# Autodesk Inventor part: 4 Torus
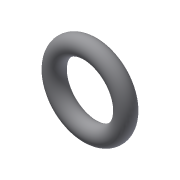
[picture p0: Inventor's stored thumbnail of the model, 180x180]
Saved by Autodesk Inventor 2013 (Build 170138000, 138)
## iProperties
Created: 2012-10
Part Number: 4 Torus
Material: Allgemein
Vendor: www.inventor-faq.de
Document SubType Name: Modeling
Designer: Administrator
Manufacturer: www.inventor-faq.de
Density: 1 g/cm^3
RuleStatus: InUse
AfterDocOpen0: inventorfaq
BeforeDocSave0: inventorfaq
Author: Administrator
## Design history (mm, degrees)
sketch "Skizze1"
  geometry: L1 (0, 2.5)-(0, -2.5); L2 (0, 0)-(-10, 0); C1 r 2.5 at (-10, 0)
  constraints: 4 end point, 1 centre point, 1 horizontal, 1 perpendicular
  dimensions: "d0" = 5 diameter of C1; "d1" = 10 distance of L2.start L2.end
revolve "Umdrehung1" sketch "Skizze1" stored, may be unused: angle "d2" = 90 deg
node "Volumenkörper1"
